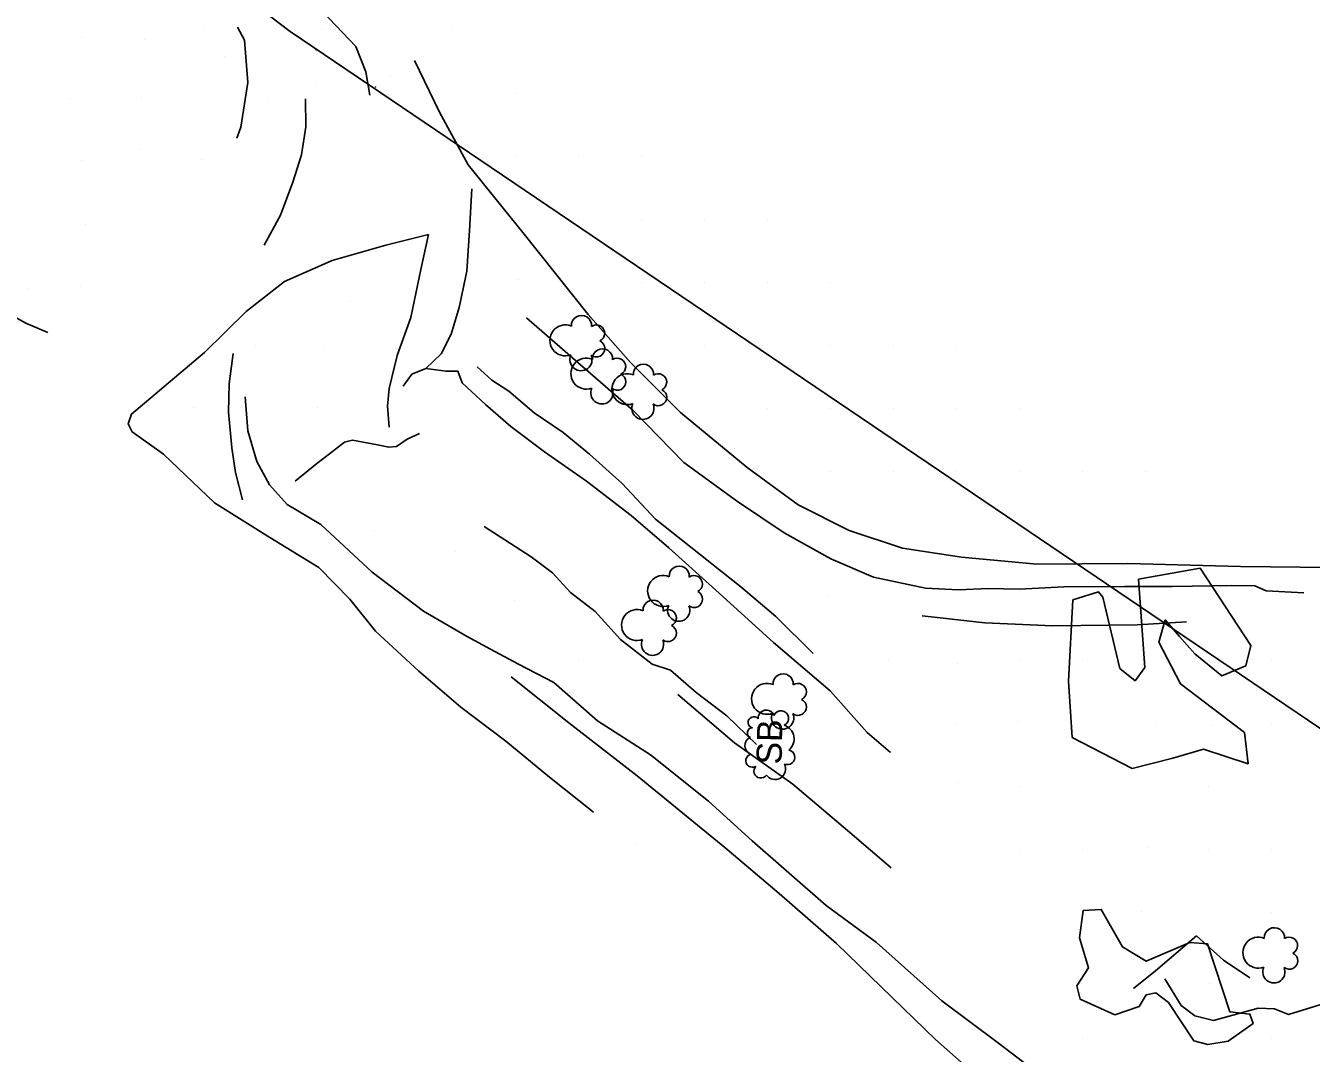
# Model space of a CAD drawing. Extents: x 19528164 to 19545171, y 7585743 to 7602745.
# Drawn here: x 19530964.4 to 19531372.6, y 7590915.4 to 7591241.6 of the extents above; entities that cross this region are included whole.
import ezdxf

# ---------------------------------------------------------------- set-up
doc = ezdxf.new("R2010")
doc.units = 0
for name, color, linetype in [('Default', 7, 'Continuous'), ('PhoBreakLine', 7, 'Continuous'), ('PhoDrainageArrow', 7, 'Continuous'), ('PhoISAEPoints', 7, 'Continuous'), ('PhoSurveyLimits', 7, 'Continuous'), ('PhoVegetation', 7, 'Continuous'), ('SurNaturalCells', 7, 'Continuous')]:
    doc.layers.add(name, color=color, linetype=linetype)

# ---------------------------------------------------------------- blocks, each defined once
blk = doc.blocks.new('SHRUB')
at = {"layer": 'Default'}
for centre, radius, start, end in [((-8.82, 2.41), 2.18, 45.3455, 236.8073), ((-5.57, 5.14), 2.08, 10.5948, 214.3611), ((-0.81, 4.83), 2.81, 22.6036, 165.7836), ((3.27, 5.33), 1.59, 0.4605, 158.7839), ((6.61, 4.92), 1.8, 311.3936, 166.4114), ((-8.06, -2.12), 3.34, 125.8289, 299.2848), ((8, 0.98), 2.6, 290.9039, 94.3687), ((8.09, -3.71), 2.42, 204.8294, 69.8871), ((-4.25, -5.95), 2.36, 157.0258, 349.7602), ((1.54, -3.45), 4.54, 220.0183, 343.6977)]:
    blk.add_arc(centre, radius, start, end, dxfattribs=at)
blk.add_text('SB', height=7.998, dxfattribs=at).set_placement((-6.62, -4.17))

msp = doc.modelspace()

# ---------------------------------------------------------------- linework, layer by layer
at = {"layer": 'PhoBreakLine'}
for points in [[(19530966.3, 7591304.05), (19530977.67, 7591296.43), (19530993.25, 7591285.05), (19531009.44, 7591274.16), (19531021.7, 7591267.48), (19531034.75, 7591265.03), (19531048.95, 7591254.24), (19531049.28, 7591253.78), (19531058.62, 7591246.12), (19531069.27, 7591234.96), (19531072.42, 7591226.96), (19531073.64, 7591219.55)], [(19531031.49, 7591205.88), (19531032.74, 7591209.36), (19531034.95, 7591223.53), (19531033.85, 7591237.04), (19531031.63, 7591241.18)], [(19531087.89, 7591230.5), (19531095.76, 7591214.2), (19531104.88, 7591197.44), (19531122.29, 7591175.9), (19531143.02, 7591149.89), (19531156.45, 7591134.66), (19531172.28, 7591118.82), (19531193.49, 7591101.35), (19531209.64, 7591089.44), (19531225.83, 7591081.32), (19531242.81, 7591075.73), (19531261.52, 7591072.89), (19531285.43, 7591070.69), (19531299.81, 7591070.76), (19531314.39, 7591070.92), (19531350.19, 7591069.94), (19531378.6, 7591069.64)], [(19531053.26, 7591218.36), (19531053.38, 7591209.47), (19531051.99, 7591200.62), (19531049.24, 7591191.96), (19531045.37, 7591181.41), (19531040.17, 7591171.94)], [(19531106.06, 7591189.76), (19531105.32, 7591176.54), (19531104.48, 7591163.66), (19531104.48, 7591163.66), (19531102.07, 7591152.11), (19531099.52, 7591143.62), (19531096.38, 7591137.46), (19531091.45, 7591132.78)], [(19530971.48, 7591144.19), (19530964.47, 7591147.13), (19530955.72, 7591152.08), (19530948.4, 7591159.18), (19530941.84, 7591165.23), (19530932.99, 7591174.06), (19530928.61, 7591179.51), (19530922.57, 7591187.9)], [(19531144.66, 7590991.92), (19531130.75, 7591003.03), (19531116.87, 7591014.43), (19531102.58, 7591025.23), (19531089.25, 7591036.7), (19531075.5, 7591049.37), (19531067.36, 7591059.52), (19531057.45, 7591069.65), (19531041.95, 7591079.1), (19531024.35, 7591090.1), (19531008.15, 7591105.59), (19530998.27, 7591112.64), (19530996.99, 7591115.23), (19530997.98, 7591118.29), (19531008.3, 7591127), (19531021.16, 7591137.81), (19531034.43, 7591150.89), (19531046.6, 7591160.38), (19531061.72, 7591167.01), (19531078.74, 7591171.89), (19531092.27, 7591175.31)], [(19531078.74, 7591171.89), (19531092.27, 7591175.31), (19531089.91, 7591164.22), (19531086.74, 7591148.92), (19531082.4, 7591136.86), (19531079.81, 7591126.41), (19531079.28, 7591120.85), (19531079.77, 7591114.12)], [(19531370.28, 7591061.52), (19531358.27, 7591062.18), (19531354.69, 7591063.81), (19531347.19, 7591063.87), (19531328.55, 7591063.58), (19531313.46, 7591063.57), (19531294.06, 7591063.44), (19531279.99, 7591062.73), (19531270.07, 7591062.98), (19531260.6, 7591062.46), (19531250.15, 7591063.08), (19531233.6, 7591066.54), (19531220.11, 7591072.4), (19531205.27, 7591080.65), (19531190.4, 7591090.55), (19531173.4, 7591102.96), (19531157.34, 7591119.4), (19531140.62, 7591133.89), (19531123.47, 7591148.9)], [(19531030.26, 7591137.57), (19531029, 7591127.89), (19531028.83, 7591118.9), (19531029.88, 7591107.59), (19531031.08, 7591099.81), (19531033.27, 7591091.08)], [(19531084.22, 7591127.19), (19531087.04, 7591130.95), (19531091.45, 7591132.78), (19531097.81, 7591131.97), (19531101.61, 7591131.95), (19531103.01, 7591128.23), (19531110.44, 7591121.37), (19531118.49, 7591114.41), (19531129.17, 7591106.35), (19531142.44, 7591097.04), (19531156.71, 7591086.12), (19531168.6, 7591075.88), (19531183.53, 7591062.39), (19531201.83, 7591045.84), (19531219.85, 7591030.46), (19531231.6, 7591017.21), (19531239.05, 7591010.9)], [(19531107.8, 7591133.35), (19531112.39, 7591129.09), (19531117.79, 7591125.62), (19531125.9, 7591118.65), (19531135.1, 7591112.41), (19531143.41, 7591105.53), (19531153.84, 7591096.27), (19531164.4, 7591084.91), (19531172.55, 7591078.47), (19531191.5, 7591063.45), (19531202.65, 7591054.08), (19531214.49, 7591042.29)], [(19531034.06, 7591123.83), (19531034.95, 7591112.98), (19531037.77, 7591103.24), (19531041.8, 7591095.84), (19531047.47, 7591089.64), (19531058.09, 7591083.2), (19531074.44, 7591068.14), (19531090.71, 7591055.74), (19531104.42, 7591047.85), (19531112.03, 7591043.67), (19531120.91, 7591038.89), (19531132.06, 7591033.04), (19531145.93, 7591020.9), (19531162.76, 7591010.15), (19531181.2, 7590995.47), (19531195.09, 7590982.86), (19531218.54, 7590962.28), (19531234.51, 7590950.56), (19531255.28, 7590932.07), (19531273.34, 7590918.6), (19531290.38, 7590905.61)], [(19531089.47, 7591112.09), (19531085.54, 7591110.37), (19531082.19, 7591108.02), (19531079.71, 7591107.76), (19531076.11, 7591108.51), (19531068.23, 7591110.04), (19531065.67, 7591109.38), (19531060.88, 7591105.67), (19531056.86, 7591102.57), (19531049.96, 7591097.03)], [(19531109.97, 7591082.57), (19531124.89, 7591072.95), (19531131.68, 7591067.95), (19531137.41, 7591061.61), (19531145.25, 7591055.66), (19531153.27, 7591046.7), (19531163.33, 7591038.89), (19531169.11, 7591036.96), (19531177.33, 7591029.92), (19531187.04, 7591022.55), (19531196.45, 7591013.37)], [(19531249.1, 7591054.25), (19531268.92, 7591052.06), (19531290.59, 7591051.1), (19531317.29, 7591051.37), (19531333.04, 7591052.38)], [(19531389.01, 7590803.2), (19531370.23, 7590817.71), (19531358.63, 7590829.09), (19531341.24, 7590842.72), (19531324.47, 7590857.16), (19531308.26, 7590872.98), (19531287.25, 7590890.86), (19531271.52, 7590903.7), (19531253.31, 7590919.77), (19531236.08, 7590936.44), (19531221.81, 7590950.2), (19531203.65, 7590966.12), (19531186.36, 7590980.73), (19531158.52, 7591003.42), (19531136.83, 7591020.26), (19531118.52, 7591034.91)], [(19531239.17, 7590974.21), (19531225.31, 7590986.06), (19531207.95, 7591000.82), (19531189.44, 7591013.94), (19531171.43, 7591029.33)], [(19531316.18, 7590935.94), (19531323.15, 7590941.51), (19531336.21, 7590952.65)], [(19531336.21, 7590952.65), (19531344.72, 7590944.96), (19531353.12, 7590939.31)]]:
    msp.add_lwpolyline(points, dxfattribs=at)
at = {"layer": 'PhoDrainageArrow'}
msp.add_lwpolyline([(19531422.01, 7591028.93), (19531420.38, 7591001.96), (19531415.41, 7590981.85), (19531413.08, 7590961.36), (19531409.06, 7590951.58), (19531402.02, 7590943.53), (19531396.18, 7590941.58), (19531389.72, 7590941.3), (19531384.69, 7590938.42), (19531383.05, 7590935.31), (19531379.42, 7590932.07), (19531365.33, 7590927.72), (19531360.98, 7590929.47), (19531355.77, 7590929.66), (19531341.52, 7590925.81), (19531335.59, 7590927.26), (19531331.27, 7590930.58), (19531326.14, 7590938.97)], dxfattribs=at)
at = {"layer": 'PhoISAEPoints'}
for p, q in [((19530981.98, 7591237.8), (19530981.98, 7591237.8)), ((19531002.13, 7591237.37), (19531002.13, 7591237.37)), ((19531020.97, 7591239.99), (19531020.97, 7591239.99)), ((19531039.26, 7591237.7), (19531039.26, 7591237.7)), ((19531058.19, 7591240.48), (19531058.19, 7591240.48)), ((19531100, 7591240), (19531100, 7591240)), ((19531027.45, 7591231.78), (19531027.45, 7591231.78)), ((19531080.09, 7591225.78), (19531080.09, 7591225.78)), ((19531056.35, 7591223.99), (19531056.35, 7591223.99)), ((19530978.77, 7591218.5), (19530978.77, 7591218.5)), ((19531001.34, 7591218.78), (19531001.34, 7591218.78)), ((19531020.65, 7591218.63), (19531020.65, 7591218.63)), ((19531041.39, 7591217.14), (19531041.39, 7591217.14)), ((19531120, 7591220), (19531120, 7591220)), ((19531140, 7591220), (19531140, 7591220)), ((19531000.52, 7591202.21), (19531000.52, 7591202.21)), ((19530982.04, 7591198.79), (19530982.04, 7591198.79)), ((19531020.26, 7591199.05), (19531020.26, 7591199.05)), ((19531120, 7591200), (19531120, 7591200)), ((19531140, 7591200), (19531140, 7591200)), ((19531160, 7591200), (19531160, 7591200)), ((19530983.31, 7591178.4), (19530983.31, 7591178.4)), ((19531000.27, 7591177.89), (19531000.27, 7591177.89)), ((19531140, 7591180), (19531140, 7591180)), ((19531160, 7591180), (19531160, 7591180)), ((19531180, 7591180), (19531180, 7591180)), ((19531200, 7591180), (19531200, 7591180)), ((19531120.81, 7591160.88), (19531120.81, 7591160.88)), ((19531160, 7591160), (19531160, 7591160)), ((19531180, 7591160), (19531180, 7591160)), ((19531200, 7591160), (19531200, 7591160)), ((19531220, 7591160), (19531220, 7591160)), ((19530965.21, 7591158.14), (19530965.21, 7591158.14)), ((19530981.68, 7591158.84), (19530981.68, 7591158.84)), ((19531067.63, 7591154.15), (19531067.63, 7591154.15)), ((19531037.28, 7591140.18), (19531037.28, 7591140.18)), ((19531180, 7591140), (19531180, 7591140)), ((19531200, 7591140), (19531200, 7591140)), ((19531220, 7591140), (19531220, 7591140)), ((19531240, 7591140), (19531240, 7591140)), ((19531260, 7591140), (19531260, 7591140)), ((19531059.07, 7591138.46), (19531059.07, 7591138.46)), ((19531017.85, 7591120.26), (19531017.85, 7591120.26)), ((19531057.15, 7591120.35), (19531057.15, 7591120.35)), ((19531200, 7591120), (19531200, 7591120)), ((19531220, 7591120), (19531220, 7591120)), ((19531240, 7591120), (19531240, 7591120)), ((19531260, 7591120), (19531260, 7591120)), ((19531280, 7591120), (19531280, 7591120)), ((19531220, 7591100), (19531220, 7591100)), ((19531240, 7591100), (19531240, 7591100)), ((19531260, 7591100), (19531260, 7591100)), ((19531280, 7591100), (19531280, 7591100)), ((19531300, 7591100), (19531300, 7591100)), ((19531320, 7591100), (19531320, 7591100)), ((19531075.17, 7591081.22), (19531075.17, 7591081.22)), ((19531100.97, 7591074.8), (19531100.97, 7591074.8)), ((19531119.51, 7591059.06), (19531119.51, 7591059.06)), ((19531218.87, 7591060.68), (19531218.87, 7591060.68)), ((19531140, 7591040), (19531140, 7591040)), ((19531238.47, 7591040.15), (19531238.47, 7591040.15)), ((19531260.4, 7591039.13), (19531260.4, 7591039.13)), ((19531280, 7591040), (19531280, 7591040)), ((19531300, 7591040), (19531300, 7591040)), ((19531320, 7591040), (19531320, 7591040)), ((19531340, 7591040), (19531340, 7591040)), ((19531360, 7591040), (19531360, 7591040)), ((19531260, 7591020), (19531260, 7591020)), ((19531279.2, 7591020.64), (19531279.2, 7591020.64)), ((19531298.64, 7591020.32), (19531298.64, 7591020.32)), ((19531323, 7591019.27), (19531323, 7591019.27)), ((19531341.01, 7591019.52), (19531341.01, 7591019.52)), ((19531360, 7591020), (19531360, 7591020)), ((19531260.62, 7591001.48), (19531260.62, 7591001.48)), ((19531280, 7591000), (19531280, 7591000)), ((19531300, 7591000), (19531300, 7591000)), ((19531321.2, 7590999.2), (19531321.2, 7590999.2)), ((19531340, 7591000), (19531340, 7591000)), ((19531359.46, 7591000.15), (19531359.46, 7591000.15)), ((19531157.99, 7590981.65), (19531157.99, 7590981.65)), ((19531320.75, 7590980.72), (19531320.75, 7590980.72)), ((19531280, 7590980), (19531280, 7590980)), ((19531300, 7590980), (19531300, 7590980)), ((19531340, 7590980), (19531340, 7590980)), ((19531360, 7590980), (19531360, 7590980)), ((19531318.69, 7590960.32), (19531318.69, 7590960.32)), ((19531360, 7590960), (19531360, 7590960)), ((19531239.03, 7590959.44), (19531239.03, 7590959.44)), ((19531340.4, 7590937.4), (19531340.4, 7590937.4)), ((19531356.89, 7590939.02), (19531356.89, 7590939.02)), ((19531300, 7590920), (19531300, 7590920)), ((19531360, 7590920), (19531360, 7590920)), ((19531338.03, 7590918.67), (19531338.03, 7590918.67))]:
    msp.add_line(p, q, dxfattribs=at)
at = {"layer": 'PhoSurveyLimits'}
msp.add_lwpolyline([(19530078.03, 7591867.16), (19530409.64, 7591574.06), (19530888.99, 7591360.57), (19531048.43, 7591239.75), (19531492.52, 7590939.32), (19532163.83, 7590474.32)], dxfattribs=at)
at = {"layer": 'PhoVegetation'}
for points in [[(19531328.66, 7591009.1), (19531315.74, 7591005.75), (19531296.64, 7591015.68), (19531295.52, 7591033.54), (19531296.91, 7591059.29), (19531305.04, 7591061.88), (19531306.38, 7591060.17), (19531311.83, 7591037.57), (19531316.65, 7591033.66), (19531319.77, 7591037.82), (19531317.78, 7591065.85), (19531337.32, 7591069.34), (19531353.38, 7591044.81), (19531351.87, 7591038.43), (19531344.22, 7591035.19), (19531335.68, 7591042.17), (19531330.74, 7591047.72), (19531326.23, 7591052.95), (19531324.25, 7591045.86), (19531331.09, 7591032.69), (19531351.4, 7591017.23), (19531352.55, 7591007.31), (19531338.43, 7591011.91)], [(19531298.16, 7590936.78), (19531301.87, 7590942.48), (19531298.97, 7590952.06), (19531300.2, 7590960.74), (19531305.91, 7590961.04), (19531312.68, 7590949.17), (19531320.19, 7590944.59), (19531334.06, 7590950.58), (19531339.61, 7590950.14), (19531346.77, 7590928.53), (19531353.11, 7590927.82), (19531354.13, 7590924.81), (19531346.24, 7590919.22), (19531339.72, 7590918.19), (19531335.3, 7590919.36), (19531327.33, 7590931.5), (19531323.28, 7590934.57), (19531320.17, 7590933.92), (19531317.96, 7590930.26), (19531310.19, 7590927.57), (19531299.21, 7590932.61)]]:
    msp.add_lwpolyline(points, close=True, dxfattribs=at)
for centre, radius, start, end in [((19531140.89, 7591146.42), 3.21, 355.0943, 183.0979), ((19531135.78, 7591141.7), 4.92, 67.3012, 290.8911), ((19531145.59, 7591143.94), 2.67, 295.6203, 124.4995), ((19531145.59, 7591139.11), 2.68, 231.8463, 64.4185), ((19531140.72, 7591135.6), 3.52, 154.5785, 23.6137), ((19531142.45, 7591131.14), 4.92, 67.3012, 290.8911), ((19531147.55, 7591135.85), 3.21, 355.0943, 183.0979), ((19531152.26, 7591133.38), 2.67, 295.6203, 124.4995), ((19531155.46, 7591126.22), 4.92, 67.3012, 290.8911), ((19531160.56, 7591130.94), 3.21, 355.0943, 183.0979), ((19531165.27, 7591128.46), 2.67, 295.6203, 124.4995), ((19531152.26, 7591128.55), 2.68, 231.8463, 64.4185), ((19531147.38, 7591125.03), 3.52, 154.5785, 23.6137), ((19531165.27, 7591123.63), 2.68, 231.8463, 64.4185), ((19531160.39, 7591120.12), 3.52, 154.5785, 23.6137), ((19531171.92, 7591066.85), 3.21, 355.0943, 183.0979), ((19531166.82, 7591062.14), 4.92, 67.3012, 290.8911), ((19531176.63, 7591064.37), 2.67, 295.6203, 124.4995), ((19531176.63, 7591059.55), 2.68, 231.8463, 64.4185), ((19531163.63, 7591056.04), 3.21, 355.0943, 183.0979), ((19531158.52, 7591051.33), 4.92, 67.3012, 290.8911), ((19531168.34, 7591053.57), 2.67, 295.6203, 124.4995), ((19531171.75, 7591056.03), 3.52, 154.5785, 23.6137), ((19531168.33, 7591048.74), 2.68, 231.8463, 64.4185), ((19531163.46, 7591045.22), 3.52, 154.5785, 23.6137), ((19531204.93, 7591032.62), 3.21, 355.0943, 183.0979), ((19531199.82, 7591027.91), 4.92, 67.3012, 290.8911), ((19531209.63, 7591030.15), 2.67, 295.6203, 124.4995), ((19531209.63, 7591025.32), 2.68, 231.8463, 64.4185), ((19531204.76, 7591021.8), 3.52, 154.5785, 23.6137), ((19531355.81, 7590947.33), 4.92, 67.3012, 290.8911), ((19531360.91, 7590952.05), 3.21, 355.0943, 183.0979), ((19531365.62, 7590949.57), 2.67, 295.6203, 124.4995), ((19531365.62, 7590944.74), 2.68, 231.8463, 64.4185), ((19531360.74, 7590941.22), 3.52, 154.5785, 23.6137)]:
    msp.add_arc(centre, radius, start, end, dxfattribs=at)
at = {"layer": 'SurNaturalCells'}
for p, q in [((19531056.61, 7591233.85), (19531056.62, 7591233.87)), ((19531056.62, 7591233.85), (19531056.62, 7591233.87)), ((19531075.48, 7591222.12), (19531075.48, 7591222.14)), ((19531075.48, 7591222.12), (19531075.48, 7591222.14))]:
    msp.add_line(p, q, dxfattribs=at)
for centre in [(19531056.62, 7591233.86), (19531075.48, 7591222.13)]:
    msp.add_circle(centre, 0.00459, dxfattribs=at)

# ---------------------------------------------------------------- block references
at = {"layer": 'PhoVegetation', "xscale": 0.9999999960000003, "yscale": 0.9999999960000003, "rotation": 88.89301078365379}
msp.add_blockref('SHRUB', (19531200.39, 7591013.72), dxfattribs=at)

doc.saveas('drawing.dxf')
